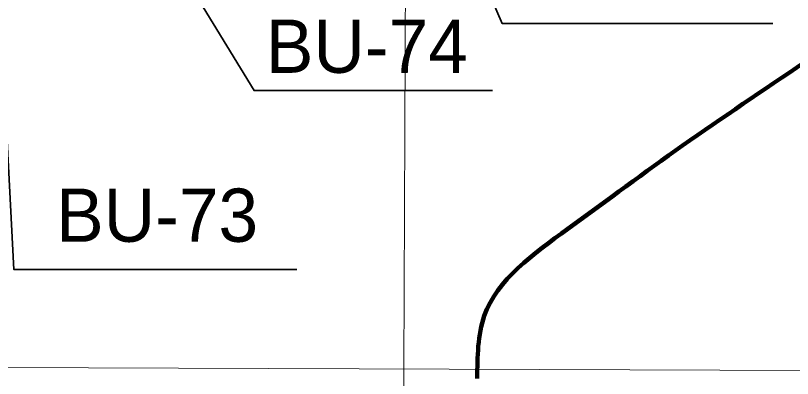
# Model space of a CAD drawing. Extents: x 553962 to 842807, y 8883888 to 9032388.
# Drawn here: x 661743 to 667576, y 8949437 to 8952165 of the extents above; entities that cross this region are included whole.
import ezdxf

# ---------------------------------------------------------------- set-up
doc = ezdxf.new("R2010")
doc.units = 0
doc.header["$LTSCALE"] = 150
for name, color, linetype, lineweight in [('1', 7, 'Continuous', 13), ('24', 7, 'Continuous', 25), ('40', 7, 'Continuous', 60), ('53', 7, 'Continuous', 106), ('9', 7, 'Continuous', 90)]:
    doc.layers.add(name, color=color, linetype=linetype, lineweight=lineweight)

msp = doc.modelspace()

# ---------------------------------------------------------------- linework, layer by layer
at = {"layer": '1'}
msp.add_line((565315.3, 8949866.8), (791497.7, 8949052.2), dxfattribs=at)
msp.add_lwpolyline([(664968.2, 9023436.8), (664657.1, 8949509), (664397.1, 8890880.2)], dxfattribs=at)
at = {"layer": '24'}
msp.add_spline([(665209.5, 8949437.1), (665261.8, 8949907.3), (665888.8, 8950560.5), (666750.9, 8951187.5), (667665.3, 8951814.5), (668344.5, 8952363.1), (668788.7, 8952911.7), (669180.6, 8953564.9), (669154.4, 8954270.2), (669755.3, 8954662.1), (670486.8, 8955027.9), (671218.3, 8955785.5), (671166.1, 8956360.3), (671531.8, 8956726), (671479.6, 8956987.3), (670957.1, 8957405.3), (670695.8, 8957849.4), (671139.9, 8958502.5), (671845.3, 8959207.9), (672394, 8958789.9), (673047.1, 8959234), (673465.1, 8959834.9), (673177.7, 8960461.9), (673987.6, 8960749.3), (675163.2, 8960879.9), (676103.7, 8960906.1), (677253.2, 8961428.6), (677697.4, 8961559.2), (678115.4, 8962133.9), (678611.8, 8962369.1), (678820.8, 8962919.9), (679291, 8963704.1), (679918, 8964226.8), (679944.1, 8964697.3), (679709, 8965272.3), (679291, 8966004.2), (678115.4, 8966945.2)], degree=3, dxfattribs=at)
at = {"layer": '40', "lineweight": 35}
for points in [[(664631.4, 8953878.8), (665395.6, 8952104.7), (667428.4, 8952104.7)], [(662816.2, 8952778.7), (663534.6, 8951601), (665322.9, 8951601)], [(661608.8, 8952579.8), (661731.1, 8950255.1), (663855.6, 8950255.1)]]:
    msp.add_lwpolyline(points, dxfattribs=at)
at = {"layer": '53'}
msp.add_spline([(665209.5, 8949437.1), (665261.8, 8949907.3), (665888.8, 8950560.5), (666750.9, 8951187.5), (667665.3, 8951814.5), (668344.5, 8952363.1), (668788.7, 8952911.7), (669180.6, 8953564.9), (669154.4, 8954270.2), (669755.3, 8954662.1), (670000.9, 8954785.2)], degree=3, dxfattribs=at)
at = {"layer": '9'}
msp.add_spline([(637260.6, 8972975.8), (641524.5, 8971056.2), (652526.1, 8965412.7), (653164.3, 8965062.8), (670790.5, 8953770.1), (686194, 8943929.9), (696283.3, 8937647.1)], degree=3, dxfattribs=at)

# ---------------------------------------------------------------- texts
at = {"layer": '40'}
for s, p in [('BU-74', (663622.6, 8951733.7)), ('BU-73', (662048.2, 8950464.2))]:
    msp.add_text(s, height=400, dxfattribs=at).set_placement(p)

doc.saveas('drawing.dxf')
